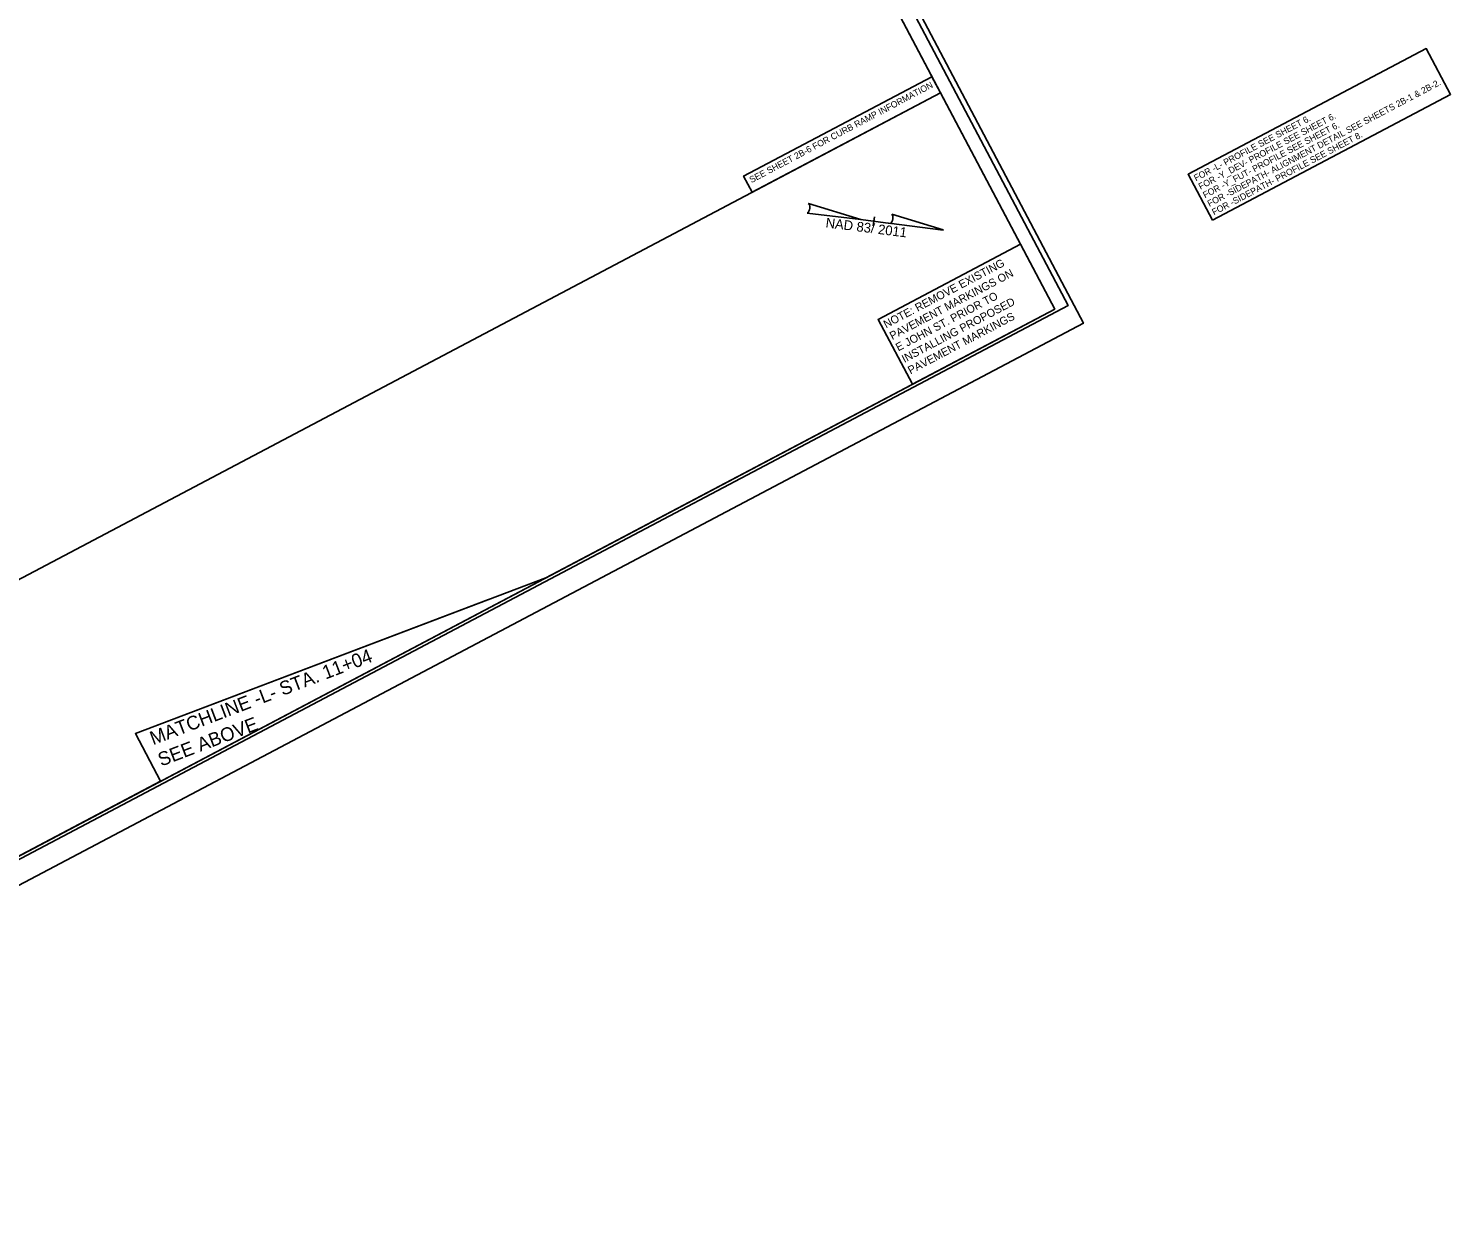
# Model space of a CAD drawing. Extents: x 1487176 to 1489663, y 497841 to 500965.
# Drawn here: x 1488420 to 1489663, y 497987 to 499031 of the extents above; entities that cross this region are included whole.
import ezdxf

# ---------------------------------------------------------------- set-up
doc = ezdxf.new("R2010")
doc.units = 0
for name, color, linetype in [('DEV TUBULAR MARKER PLAN VIEW CELL', 7, 'Continuous'), ('MARK LEFT TURN ARROW CELL', 7, 'Continuous'), ('MARK STRAIGHT ARROW CELL', 7, 'Continuous'), ('Prop Mkg 3ft Min Skp 9ft White', 7, 'Continuous'), ('Prop Mkg Solid White Crosswalks', 7, 'Continuous'), ('Prop Mkg Solid White Lane Line', 7, 'Continuous'), ('Prop Mkg Solid White Stop Bar', 7, 'Continuous'), ('Prop Mkg Solid Yellow Lane Line', 7, 'Continuous'), ('Scratch_Level_1', 7, 'Continuous')]:
    doc.layers.add(name, color=color, linetype=linetype)

msp = doc.modelspace()

# ---------------------------------------------------------------- linework, layer by layer
at = {"layer": 'DEV TUBULAR MARKER PLAN VIEW CELL'}
for points in [[(1488120.4, 498369.2), (1487949.5, 498194.2), (1487512.6, 499019.7), (1488662.1, 499625.8), (1488771.3, 499418.8), (1488936.6, 499506), (1489317.2, 498785.2), (1488242.7, 498217.8)], [(1489217.3, 498974.3), (1489217.3, 498974.3), (1489317.2, 498785.2), (1488872, 498550.1), (1488513.2, 498414), (1488535.2, 498372.3), (1488098.7, 498141.8), (1487999.8, 498331.5)]]:
    msp.add_lwpolyline(points, close=True, dxfattribs=at)
at = {"layer": 'MARK LEFT TURN ARROW CELL'}
for points in [[(1489455.1, 498863), (1489663.4, 498973), (1489642.1, 499013.2), (1489433.8, 498903.2)], [(1489052.6, 498887.4), (1489217.3, 498974.3), (1489209.8, 498988.5), (1489045.1, 498901.6)], [(1489192.7, 498719.5), (1489317.2, 498785.2), (1489287.2, 498842), (1489162.7, 498776.3)]]:
    msp.add_lwpolyline(points, close=True, dxfattribs=at)
at = {"layer": 'MARK STRAIGHT ARROW CELL'}
msp.add_lwpolyline([(1488830.6, 499742), (1487342.4, 498956.2), (1487854.1, 497987.1), (1489342.3, 498772.9)], close=True, dxfattribs=at)
at = {"layer": 'Prop Mkg 3ft Min Skp 9ft White'}
msp.add_line((1488513.2, 498414), (1488822.1, 498531.2), dxfattribs=at)
at = {"layer": 'Prop Mkg Solid White Lane Line'}
for points in [[(1488826.9, 499713.7), (1487500.5, 499013.3), (1487990.8, 498084.8), (1489317.2, 498785.2)], [(1487999.8, 498331.5), (1489217.3, 498974.3), (1489317.2, 498785.2), (1488099.7, 498142.3)]]:
    msp.add_lwpolyline(points, close=True, dxfattribs=at)
at = {"layer": 'Prop Mkg Solid White Stop Bar'}
for p, q in [((1489100.8, 498869.3), (1489147.5, 498863.5)), ((1489147.5, 498863.5), (1489101.7, 498877.6)), ((1489147.5, 498863.5), (1489173.5, 498860.2)), ((1489159.5, 498866), (1489158.5, 498858)), ((1489159.1, 498862.5), (1489159.5, 498866)), ((1489159.5, 498866), (1489159.5, 498866.1)), ((1489219.5, 498854.4), (1489172.1, 498860.4)), ((1489172.1, 498860.4), (1489173.5, 498860.2)), ((1489174.6, 498868.4), (1489219.6, 498854.5)), ((1489219.5, 498854.4), (1489219.6, 498854.5)), ((1489219.5, 498854.4), (1489219.6, 498854.5))]:
    msp.add_line(p, q, dxfattribs=at)
for centre, start_param, end_param in [((1489101, 498873.5), 0.201328, 3.141593), ((1489173.6, 498864.4), 0.216388, 2.908219)]:
    msp.add_ellipse(centre, major_axis=(-0.56, -4.19), ratio=0.461098, start_param=start_param, end_param=end_param, dxfattribs=at)
at = {"layer": 'Scratch_Level_1'}
msp.add_lwpolyline([(1488835.9, 499722.2), (1487363.2, 498944.6), (1487856.2, 498010.8), (1489329, 498788.5)], close=True, dxfattribs=at)

# ---------------------------------------------------------------- texts
at = {"layer": 'Prop Mkg Solid White Crosswalks'}
for s, p in [('MATCHLINE -L- STA. 11+04 ', (1488528.6, 498403.7)), ('SEE ABOVE', (1488535.7, 498385))]:
    msp.add_text(s, height=12, rotation=20.8513, dxfattribs=at).set_placement(p)
at = {"layer": 'Prop Mkg Solid White Stop Bar'}
msp.add_text('NAD 83/ 2011', height=8.5, rotation=352.8557, dxfattribs=at).set_placement((1489116.5, 498856.8))
at = {"layer": 'Prop Mkg Solid Yellow Lane Line'}
for s, height, rotation, p in [('SEE SHEET 2B-6 FOR CURB RAMP INFORMATION', 5.625, 27.8351, (1489052, 498895.4)), ('FOR -SIDEPATH- ALIGNMENT DETAIL SEE SHEETS 2B-1 & 2B-2.', 5.625, 27.8351, (1489452.5, 498874.6)), ('FOR -Y_DEV- PROFILE SEE SHEET 6.', 5.625, 27.8351, (1489444.7, 498889.6)), ('FOR -L- PROFILE SEE SHEET 6.', 5.625, 27.8351, (1489440.7, 498897)), ('FOR -Y_FUT- PROFILE SEE SHEET 6.', 5.625, 27.8351, (1489448.6, 498882.1)), ('FOR -SIDEPATH- PROFILE SEE SHEET 8.', 5.625, 27.8351, (1489456.5, 498867.2)), ('NOTE: REMOVE EXISTING  ', 7, 27.835, (1489169.7, 498768.3)), ('PAVEMENT MARKINGS ON ', 7, 27.835, (1489175.1, 498758.2)), ('E JOHN ST. PRIOR TO ', 7, 27.835, (1489180.4, 498748.2)), ('INSTALLING PROPOSED ', 7, 27.835, (1489185.7, 498738.1)), ('PAVEMENT MARKINGS', 7, 27.835, (1489191, 498728.1))]:
    msp.add_text(s, height=height, rotation=rotation, dxfattribs=at).set_placement(p)

doc.saveas('drawing.dxf')
